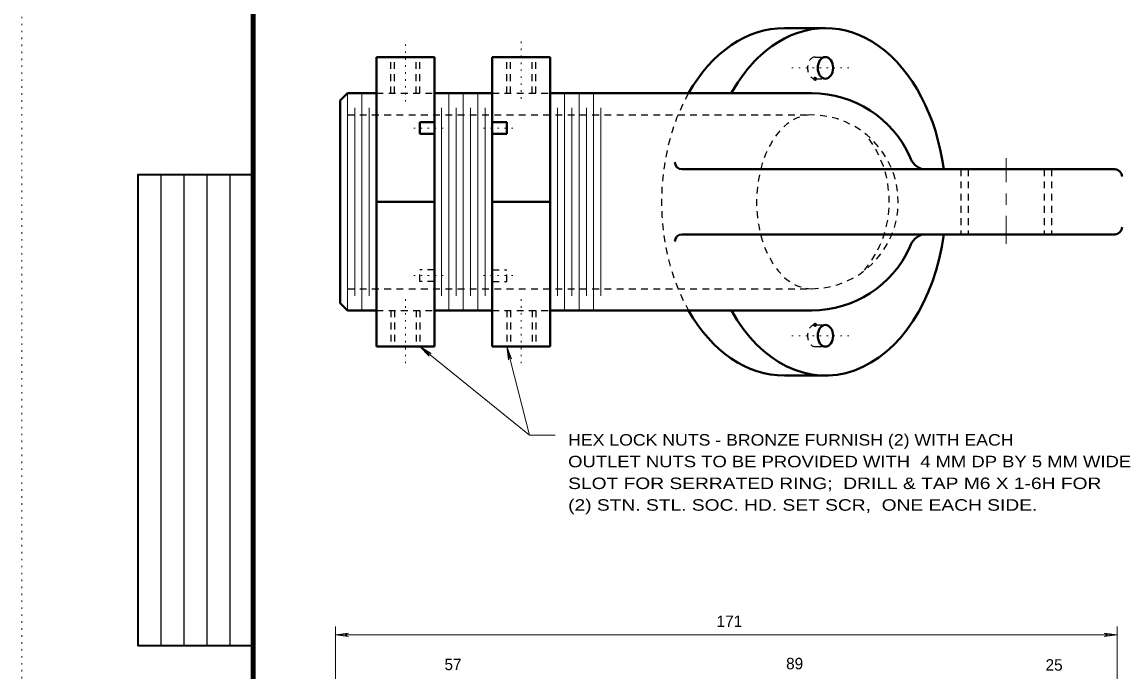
# Model space of a CAD drawing. Extents: x 312583 to 312854, y 144419 to 144597.
# Drawn here: x 312601.2 to 312674, y 144489 to 144532 of the extents above; entities that cross this region are included whole.
import ezdxf

# ---------------------------------------------------------------- set-up
doc = ezdxf.new("R2010")
doc.units = 0
doc.header["$LTSCALE"] = 0.3
doc.header["$PDMODE"] = 32
doc.header["$PDSIZE"] = 0.15
doc.linetypes.add('DOTTED', pattern=[1.5, 0.3, -1.2])
doc.linetypes.add('SHORT_DASHED', pattern=[2.7, 1.5, -1.2])
for name, color, linetype, lineweight in [('1', 7, 'Continuous', 40), ('2', 7, 'Continuous', 13), ('62', 7, 'DOTTED', 13)]:
    doc.layers.add(name, color=color, linetype=linetype, lineweight=lineweight)

msp = doc.modelspace()

# ---------------------------------------------------------------- linework, layer by layer
at = {"layer": '1'}
for p, q in [((312654.3783, 144531.5553), (312651.6643, 144531.5553)), ((312624.6623, 144529.6386), (312624.6623, 144510.472)), ((312628.4956, 144510.472), (312628.4956, 144529.6386)), ((312632.3289, 144529.6386), (312632.3289, 144510.472)), ((312636.1623, 144510.472), (312636.1623, 144529.6386)), ((312622.7456, 144527.239), (312622.2626, 144526.756)), ((312622.7456, 144527.239), (312624.6623, 144527.239)), ((312628.4956, 144527.239), (312632.3289, 144527.239)), ((312636.1623, 144527.239), (312653.4736, 144527.239)), ((312622.2626, 144526.756), (312622.2626, 144513.347)), ((312627.5373, 144525.3223), (312627.5373, 144524.5556)), ((312628.4956, 144525.3223), (312627.5373, 144525.3223)), ((312632.3289, 144525.3223), (312633.2873, 144525.3223)), ((312633.2873, 144525.3223), (312633.2873, 144524.5556)), ((312628.4956, 144524.5556), (312627.5373, 144524.5556)), ((312632.3289, 144524.5556), (312633.2873, 144524.5556)), ((312673.5373, 144522.2096), (312644.8946, 144522.2096)), ((312673.5373, 144517.901), (312644.8946, 144517.901)), ((312622.7456, 144512.864), (312622.2626, 144513.347)), ((312622.7456, 144512.864), (312624.6623, 144512.864)), ((312628.4956, 144512.864), (312632.3289, 144512.864)), ((312636.1623, 144512.864), (312653.4736, 144512.864)), ((312654.3783, 144508.5553), (312651.6643, 144508.5553))]:
    msp.add_line(p, q, dxfattribs=at)
at = {"layer": '1', "linetype": 'SHORT_DASHED', "lineweight": 25}
for p, q in [((312625.6206, 144527.239), (312625.6206, 144529.6386)), ((312625.8583, 144527.239), (312625.8583, 144529.6386)), ((312627.2996, 144527.239), (312627.2996, 144529.6386)), ((312627.5373, 144527.239), (312627.5373, 144529.6386)), ((312633.2873, 144527.239), (312633.2873, 144529.6386)), ((312633.5249, 144527.239), (312633.5249, 144529.6386)), ((312634.9663, 144527.239), (312634.9663, 144529.6386)), ((312635.2039, 144527.239), (312635.2039, 144529.6386)), ((312653.7036, 144529.6386), (312654.3783, 144529.6386)), ((312653.7036, 144528.1973), (312654.3783, 144528.1973)), ((312624.6623, 144527.239), (312628.4956, 144527.239)), ((312632.3289, 144527.239), (312636.1623, 144527.239)), ((312622.7456, 144525.8053), (312653.4736, 144525.8053)), ((312663.3483, 144522.2096), (312663.3483, 144517.901)), ((312663.8313, 144522.2096), (312663.8313, 144517.901)), ((312668.8683, 144522.2096), (312668.8683, 144517.901)), ((312669.3436, 144522.2096), (312669.3436, 144517.901)), ((312628.4956, 144515.555), (312627.5373, 144515.555)), ((312627.5373, 144514.7883), (312627.5373, 144515.555)), ((312632.3289, 144515.555), (312633.2873, 144515.555)), ((312633.2873, 144514.7883), (312633.2873, 144515.555)), ((312628.4956, 144514.7883), (312627.5373, 144514.7883)), ((312632.3289, 144514.7883), (312633.2873, 144514.7883)), ((312622.7456, 144514.3053), (312653.4736, 144514.3053)), ((312624.6623, 144512.864), (312628.4956, 144512.864)), ((312625.6206, 144512.8716), (312625.6206, 144510.472)), ((312625.8583, 144512.8716), (312625.8583, 144510.472)), ((312627.2996, 144512.8716), (312627.2996, 144510.472)), ((312627.5373, 144512.8716), (312627.5373, 144510.472)), ((312632.3289, 144512.864), (312636.1623, 144512.864)), ((312633.2873, 144512.8716), (312633.2873, 144510.472)), ((312633.5249, 144512.8716), (312633.5249, 144510.472)), ((312634.9663, 144512.8716), (312634.9663, 144510.472)), ((312635.2039, 144512.8716), (312635.2039, 144510.472)), ((312653.7036, 144511.9133), (312654.3783, 144511.9133)), ((312653.7036, 144510.472), (312654.3783, 144510.472))]:
    msp.add_line(p, q, dxfattribs=at)
at = {"layer": '1', "linetype": 'DOTTED', "lineweight": 13}
for p, q in [((312655.9346, 144528.918), (312651.8176, 144528.918)), ((312629.0706, 144524.939), (312626.9546, 144524.939)), ((312631.7539, 144524.939), (312633.8699, 144524.939)), ((312629.0706, 144515.1716), (312626.9546, 144515.1716)), ((312631.7539, 144515.1716), (312633.8699, 144515.1716)), ((312655.9346, 144511.1926), (312651.8176, 144511.1926))]:
    msp.add_line(p, q, dxfattribs=at)
at = {"layer": '1', "lineweight": 13}
for p, q in [((312622.7456, 144527.239), (312622.7456, 144512.864)), ((312623.7039, 144527.239), (312623.7039, 144512.864)), ((312629.4539, 144527.239), (312629.4539, 144512.864)), ((312630.4123, 144527.239), (312630.4123, 144512.864)), ((312631.3706, 144527.239), (312631.3706, 144512.864)), ((312637.1206, 144527.239), (312637.1206, 144512.864)), ((312638.0789, 144527.239), (312638.0789, 144512.864)), ((312639.0373, 144527.239), (312639.0373, 144512.864)), ((312623.2286, 144526.2806), (312623.2286, 144513.8223)), ((312624.1869, 144526.2806), (312624.1869, 144513.8223)), ((312628.9786, 144526.2806), (312628.9786, 144513.8223)), ((312629.9369, 144526.2806), (312629.9369, 144513.8223)), ((312630.8953, 144526.2806), (312630.8953, 144513.8223)), ((312631.8536, 144526.2806), (312631.8536, 144513.8223)), ((312636.6453, 144526.2806), (312636.6453, 144513.8223)), ((312637.6036, 144526.2806), (312637.6036, 144513.8223)), ((312638.5619, 144526.2806), (312638.5619, 144513.8223)), ((312639.5203, 144526.2806), (312639.5203, 144513.8223))]:
    msp.add_line(p, q, dxfattribs=at)
at = {"layer": '1', "lineweight": 25}
for p, q in [((312610.4087, 144490.6573), (312610.4087, 144521.8756)), ((312611.9315, 144490.6573), (312611.9315, 144521.8756)), ((312613.4543, 144490.6573), (312613.4543, 144521.8756)), ((312614.9772, 144490.6573), (312614.9772, 144521.8756))]:
    msp.add_line(p, q, dxfattribs=at)
at = {"layer": '1', "lineweight": 158}
msp.add_lwpolyline([(312616.5, 144423.1446), (312616.5, 144585.0846), (312849, 144585.0846)], dxfattribs=at)
at = {"layer": '1', "lineweight": 35}
msp.add_lwpolyline([(312616.5, 144490.6573), (312608.8858, 144490.6573), (312608.8858, 144521.8756), (312616.5, 144521.8756)], dxfattribs=at)
at = {"layer": '1'}
for centre, radius, start, end in [((312653.475, 144520.1166), 7.1261, 24.19842, 90.01117), ((312661.162, 144523.4094), 1.2439, 197.39141, 254.69184), ((312644.8908, 144522.6888), 0.4792, 180, 270), ((312673.5334, 144521.7305), 0.4792, 0, 90), ((312644.8908, 144517.4218), 0.4792, 90, 180), ((312661.162, 144516.7012), 1.2439, 105.30816, 162.60859), ((312673.5334, 144518.3801), 0.4792, 270, 0), ((312653.475, 144519.994), 7.1261, 269.98883, 335.80158)]:
    msp.add_arc(centre, radius, start, end, dxfattribs=at)
at = {"layer": '1', "linetype": 'SHORT_DASHED', "lineweight": 25}
for centre, radius, start, end in [((312653.4506, 144520.0553), 5.75, 270.22964, 89.77036), ((312651.4985, 144520.0756), 7.1118, 320.29106, 39.12528)]:
    msp.add_arc(centre, radius, start, end, dxfattribs=at)
at = {"layer": '1'}
for centre, ratio, start_param, end_param in [((312651.6643, 144520.0553), 0.707333, 3.1415927, 4.0376844), ((312654.3783, 144520.0553), 0.693333, 1.759243, 3.6030269), ((312654.3783, 144520.0553), 0.693333, 3.6030269, 4.0376844), ((312654.3783, 144520.0553), 0.693333, 5.3876904, 7.6655349), ((312651.6643, 144520.0553), 0.707333, 5.3879476, 6.2831853)]:
    msp.add_ellipse(centre, major_axis=(0, -11.5), ratio=ratio, start_param=start_param, end_param=end_param, dxfattribs=at)
at = {"layer": '1', "linetype": 'SHORT_DASHED', "lineweight": 25}
for centre, major_axis, ratio, start_param, end_param in [((312653.7036, 144528.918), (0, -0.7207), 0.702128, 3.1415927, 6.2831853), ((312651.6643, 144520.0553), (0, -11.5), 0.707333, 4.0376844, 5.3879238), ((312653.4736, 144520.0553), (0, 5.75), 0.634672, 6.2831853, 9.424778), ((312653.7036, 144511.1926), (0, 0.7207), 0.702128, 0, 3.1415927)]:
    msp.add_ellipse(centre, major_axis=major_axis, ratio=ratio, start_param=start_param, end_param=end_param, dxfattribs=at)
at = {"layer": '1'}
for centre, major_axis in [((312654.3783, 144528.918), (0, -0.7207)), ((312654.3783, 144511.1926), (0, 0.7207))]:
    msp.add_ellipse(centre, major_axis=major_axis, ratio=0.702128, dxfattribs=at)
for p in [(312653.7036, 144528.1973), (312653.7036, 144511.9133)]:
    msp.add_point(p, dxfattribs=at)
at = {"layer": '2', "linetype": 'DOTTED'}
for p, q in [((312626.5789, 144526.6946), (312626.5789, 144530.712)), ((312634.2456, 144526.8786), (312634.2456, 144530.712)), ((312626.5789, 144513.6076), (312626.5789, 144509.3756)), ((312634.2456, 144513.6076), (312634.2456, 144509.3756))]:
    msp.add_line(p, q, dxfattribs=at)
at = {"layer": '2', "lineweight": 40}
for p, q in [((312628.4956, 144529.6386), (312624.6623, 144529.6386)), ((312632.3289, 144529.6386), (312636.1623, 144529.6386)), ((312628.4956, 144520.0553), (312624.6623, 144520.0553)), ((312632.3289, 144520.0553), (312636.1623, 144520.0553)), ((312628.4956, 144510.472), (312624.6623, 144510.472)), ((312632.3289, 144510.472), (312636.1623, 144510.472))]:
    msp.add_line(p, q, dxfattribs=at)
at = {"layer": '2'}
for p, q in [((312666.3459, 144522.938), (312666.3459, 144521.3663)), ((312666.3459, 144520.6073), (312666.3459, 144519.8483)), ((312666.3459, 144519.1353), (312666.3459, 144517.28)), ((312627.5373, 144510.472), (312628.1429, 144509.8433)), ((312627.5373, 144510.472), (312628.2809, 144510.012)), ((312633.2873, 144510.472), (312633.3946, 144509.6056)), ((312633.2873, 144510.472), (312633.6016, 144509.6593)), ((312628.1429, 144509.8433), (312627.9973, 144510.104)), ((312628.2809, 144510.012), (312627.9973, 144510.104)), ((312633.3946, 144509.6056), (312633.4329, 144509.897)), ((312633.6016, 144509.6593), (312633.4329, 144509.897)), ((312634.7823, 144504.6146), (312636.4919, 144504.6146)), ((312621.9437, 144483.1132), (312621.9437, 144491.9452)), ((312621.9437, 144491.3932), (312622.81, 144491.5006)), ((312622.81, 144491.5006), (312622.534, 144491.3932)), ((312672.8274, 144491.5006), (312673.1034, 144491.3932)), ((312673.6937, 144491.3932), (312672.8274, 144491.5006)), ((312673.6937, 144479.8856), (312673.6937, 144491.9452)), ((312621.9437, 144491.3932), (312673.6937, 144491.3932)), ((312621.9437, 144491.3932), (312622.81, 144491.2859)), ((312622.81, 144491.2859), (312622.534, 144491.3932)), ((312672.8274, 144491.2859), (312673.1034, 144491.3932)), ((312673.6937, 144491.3932), (312672.8274, 144491.2859))]:
    msp.add_line(p, q, dxfattribs=at)
msp.add_lwpolyline([(312627.5373, 144510.472), (312634.7823, 144504.6146), (312633.2873, 144510.472)], dxfattribs=at)
at = {"layer": '62'}
msp.add_line((312601.2, 144418.5846), (312601.2, 144596.7846), dxfattribs=at)

# ---------------------------------------------------------------- texts
at = {"layer": '2'}
for s, width, p in [('HEX LOCK NUTS - BRONZE FURNISH (2) WITH EACH', 1.15, (312637.3506, 144503.916)), ('OUTLET NUTS TO BE PROVIDED WITH  4 MM DP BY 5 MM WIDE', 1.2, (312637.3506, 144502.4823)), ('SLOT FOR SERRATED RING;  DRILL & TAP M6 X 1-6H FOR', 1.25, (312637.3506, 144501.041)), ('(2) STN. STL. SOC. HD. SET SCR,  ONE EACH SIDE.', 1.25, (312637.3506, 144499.6073))]:
    msp.add_text(s, height=0.76, dxfattribs=dict(at, width=width)).set_placement(p)
for s, p in [('171 ', (312647.1772, 144491.9078)), ('57', (312629.1644, 144489.054)), ('89', (312651.7777, 144489.1076)), ('25', (312668.9522, 144489.0175))]:
    msp.add_text(s, height=0.76, dxfattribs=at).set_placement(p)

doc.saveas('drawing.dxf')
